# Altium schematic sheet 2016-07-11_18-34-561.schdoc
size 328 x 139 mm; SheetNumber: 1; SheetTotal: 1
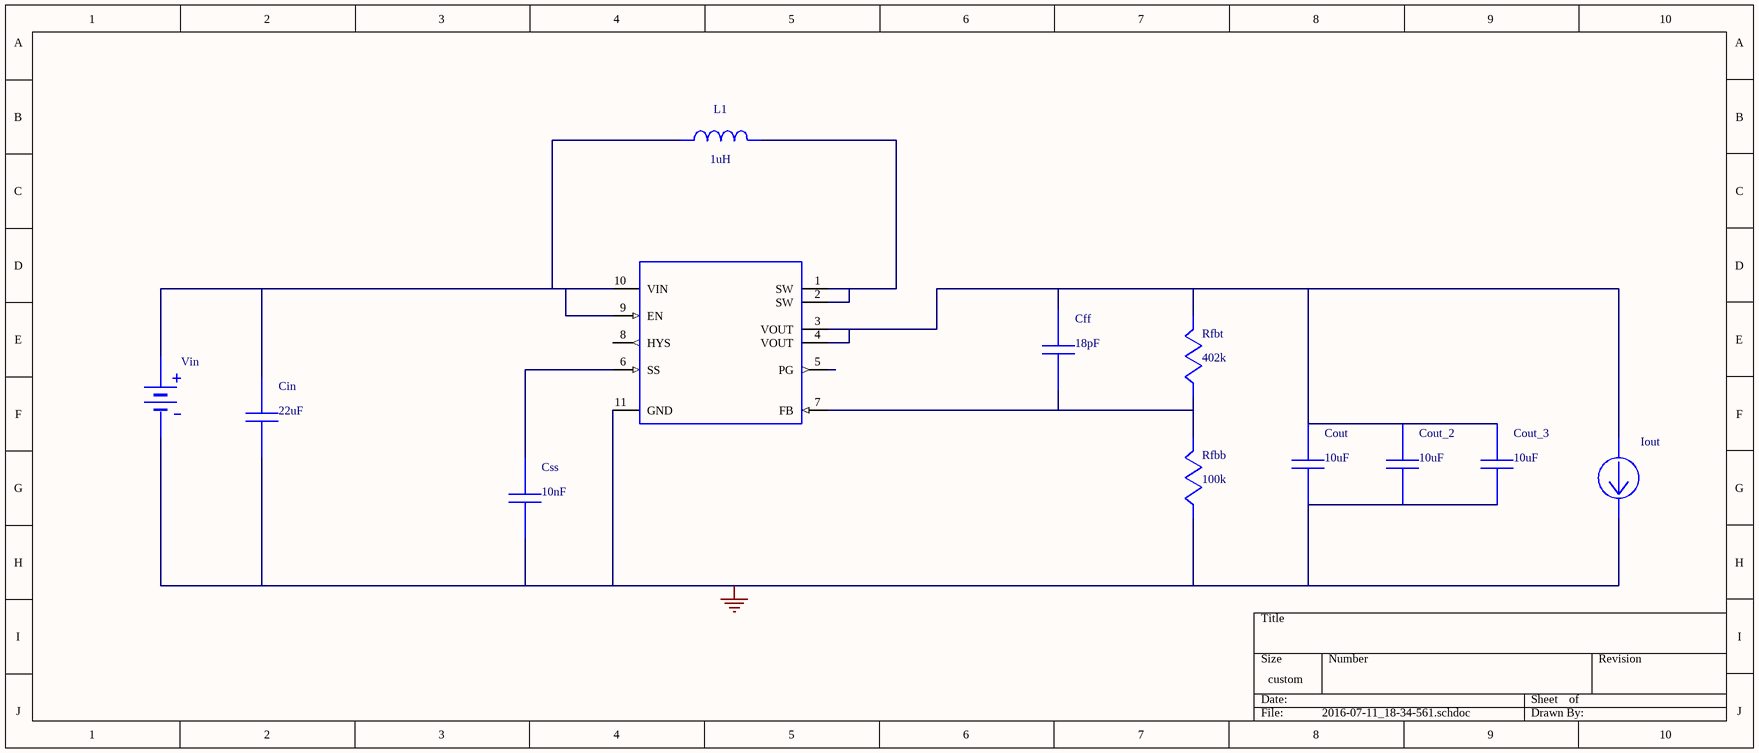
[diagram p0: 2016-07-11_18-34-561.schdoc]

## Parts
Cff  value 18pF  (hidden comment: C0603C180K5GACTU)
Cin  value 22uF  (hidden comment: JMK212BJ226MG-T)
Cout  value 10uF  (hidden comment: LMK212BJ106KG-T)
Cout_2  value 10uF  (hidden comment: LMK212BJ106KG-T)
Cout_3  value 10uF  (hidden comment: LMK212BJ106KG-T)
Css  value 10nF  (hidden comment: GRM033R60J103KA01D)
Iout  WB_CURRENT_LOAD  (value not drawn)
L1  value 1uH  (hidden comment: SRU1028-1R0Y)
Rfbb  value 100k  (hidden comment: CRCW0402100KFKED)
Rfbt  value 402k  (hidden comment: CRCW0402402KFKED)
U1  TPS61230DRCR  (value not drawn)
Vin  WB_BATTERY  (value not drawn)

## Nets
0: Cin.2 Cout.2 Cout_2.2 Cout_3.2 Css.2 Iout.2(-) Rfbb.2 U1.11(GND) Vin.2(-)
NetCff_1: Cff.1 Cout.1 Cout_2.1 Cout_3.1 Iout.1(+) Rfbt.1 U1.3(VOUT) U1.4(VOUT)
NetCff_2: Cff.2 Rfbb.1 Rfbt.2 U1.7(FB)
NetCin_1: Cin.1 L1.1 U1.9(EN) U1.10(VIN) Vin.1(+)
NetCss_1: Css.1 U1.6(SS)
NetL1_2: L1.2 U1.1(SW) U1.2(SW)

Not connected (* = marked no-connect by the designer): U1 5(PG) 8(HYS)

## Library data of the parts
Cff = C0603C180K5GACTU: Manufacturer Name: Kemet
Cin = JMK212BJ226MG-T: Manufacturer Name: Taiyo Yuden
Cout Cout_2 Cout_3 = LMK212BJ106KG-T: Manufacturer Name: Taiyo Yuden
Css = GRM033R60J103KA01D: GRM033R60J103KA0; Manufacturer Name: MuRata
L1 = SRU1028-1R0Y: Manufacturer Name: Bourns
Rfbb = CRCW0402100KFKED: Manufacturer Name: Vishay-Dale
Rfbt = CRCW0402402KFKED: Manufacturer Name: Vishay-Dale
U1 = TPS61230DRCR: Manufacturer Name: Texas Instruments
